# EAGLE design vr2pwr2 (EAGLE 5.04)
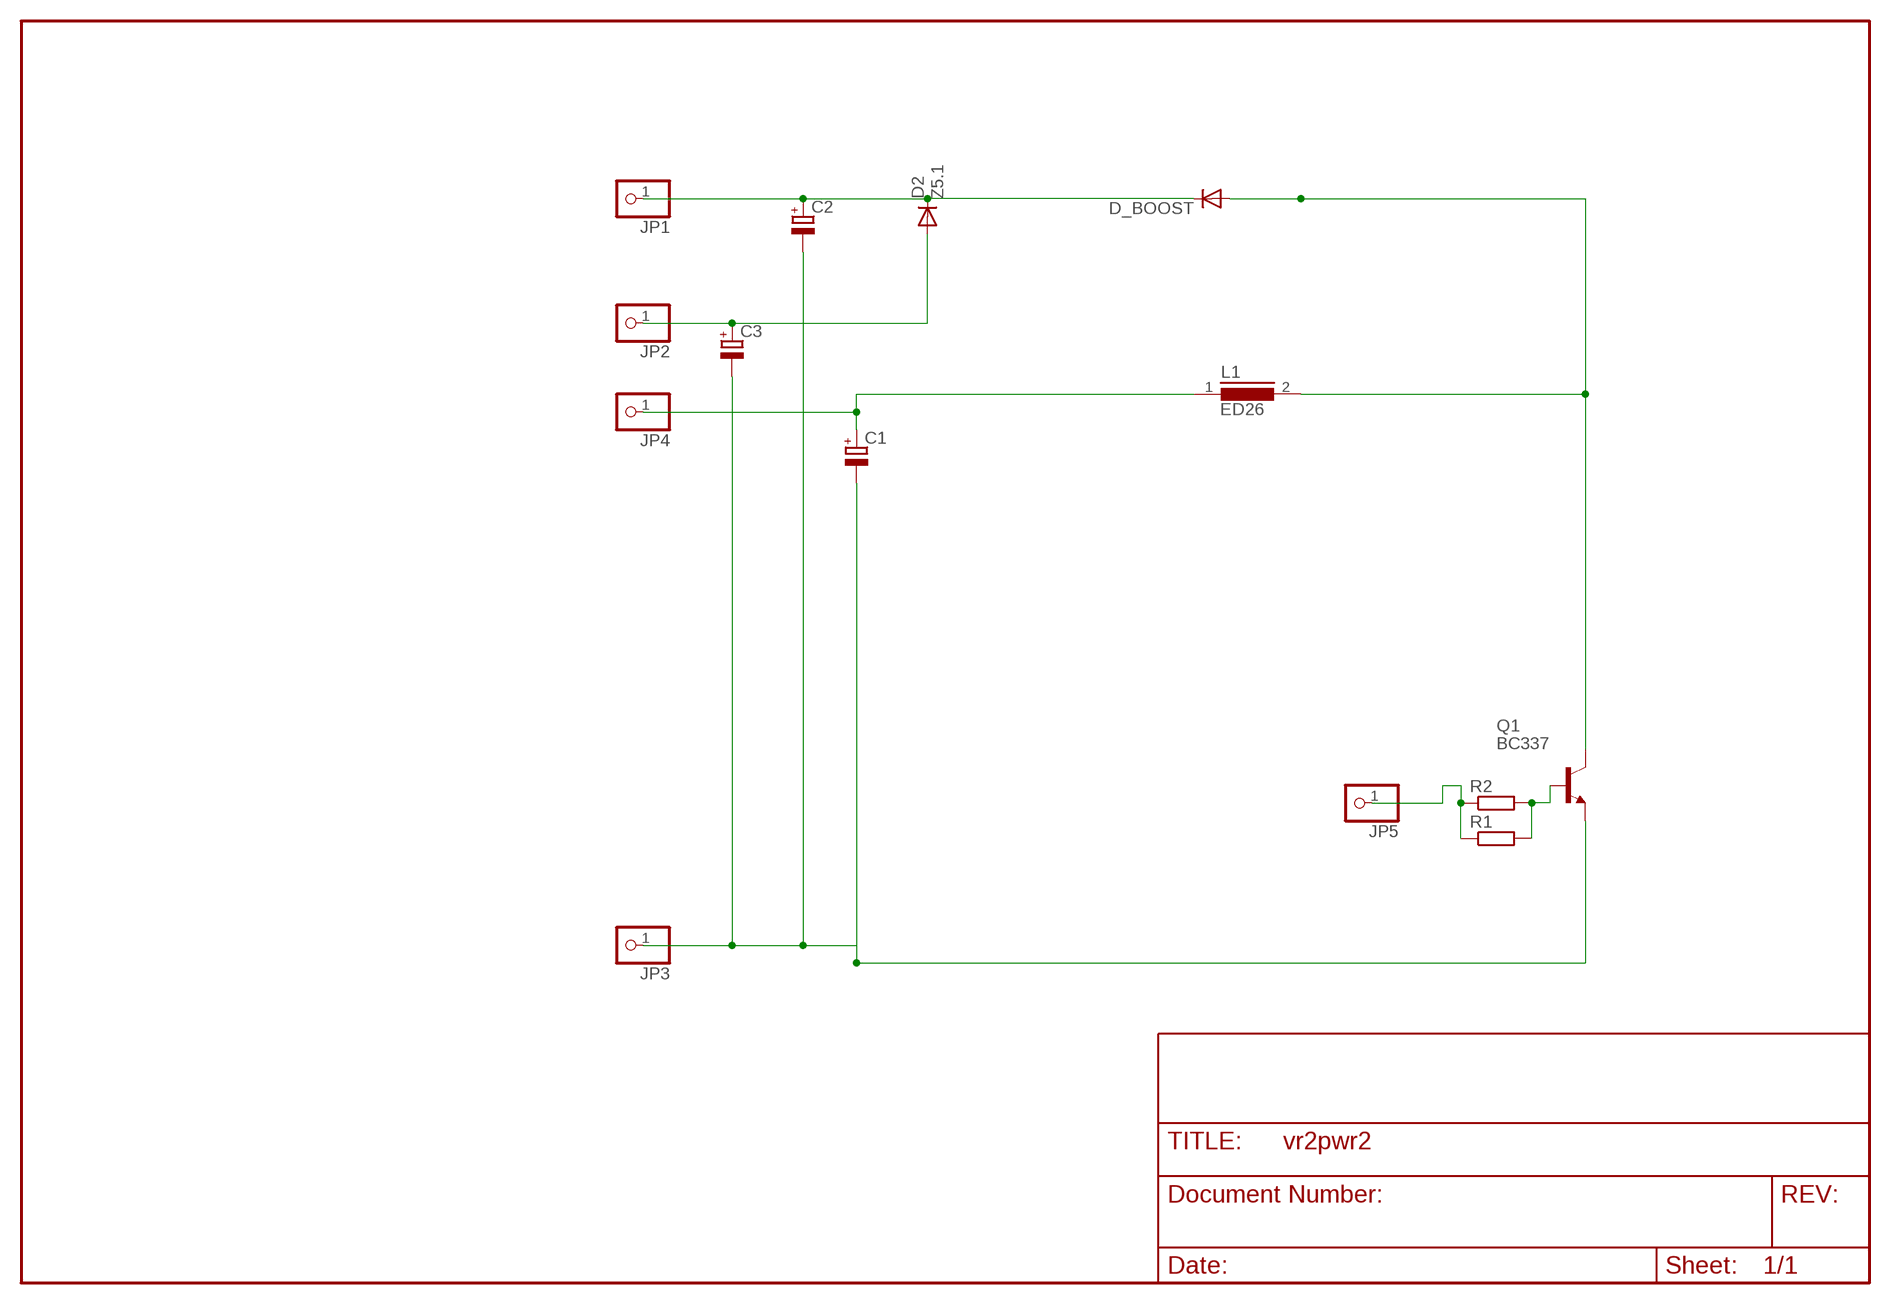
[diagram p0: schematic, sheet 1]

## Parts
C1  CPOL-EUE2.5-7  [E2,5-7]
C2  CPOL-EUE2.5-7  [E2,5-7]
C3  CPOL-EUE2-4  [E2-4]
D2  Z5.1  DIODE-D-2.5  [D-2.5]
D_BOOST  DIODE-D-10  [D-10]
JP1  PINHD-1X1  [1X01]
JP2  PINHD-1X1  [1X01]
JP3  PINHD-1X1  [1X01]
JP4  PINHD-1X1  [1X01]
JP5  PINHD-1X1  [1X01]
L1  ED26  [ED26]
Q1  BC337  [TO92]
R1  R-EU_R1206  [R1206]
R2  R-EU_R1206  [R1206]

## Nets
GND: C1.- C2.- C3.- JP3.1 Q1.1(E)
HOTSPOT: D_BOOST.A L1.2 Q1.3(C)
LOAD: C2.+ D2.C D_BOOST.C JP1.1
N$1: Q1.2(B) R1.2 R2.2
N$2: C1.+ JP4.1 L1.1
N$3: JP5.1 R1.1 R2.1
N$4: C3.+ D2.A JP2.1

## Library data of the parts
C1-C3 = rcl(2):CPOL-EU: POLARIZED CAPACITOR, European symbol
D2 D_BOOST = diode:DIODE-: DIODE
JP1-JP5 = pinhead:PINHD-1X1: PIN HEADER
L1 = inductors:ED26: INDUCTOR
Q1 = transistor-npn:BC337*: NPN Transistor
R1 R2 = rcl-2:R-EU_: RESISTOR, European symbol

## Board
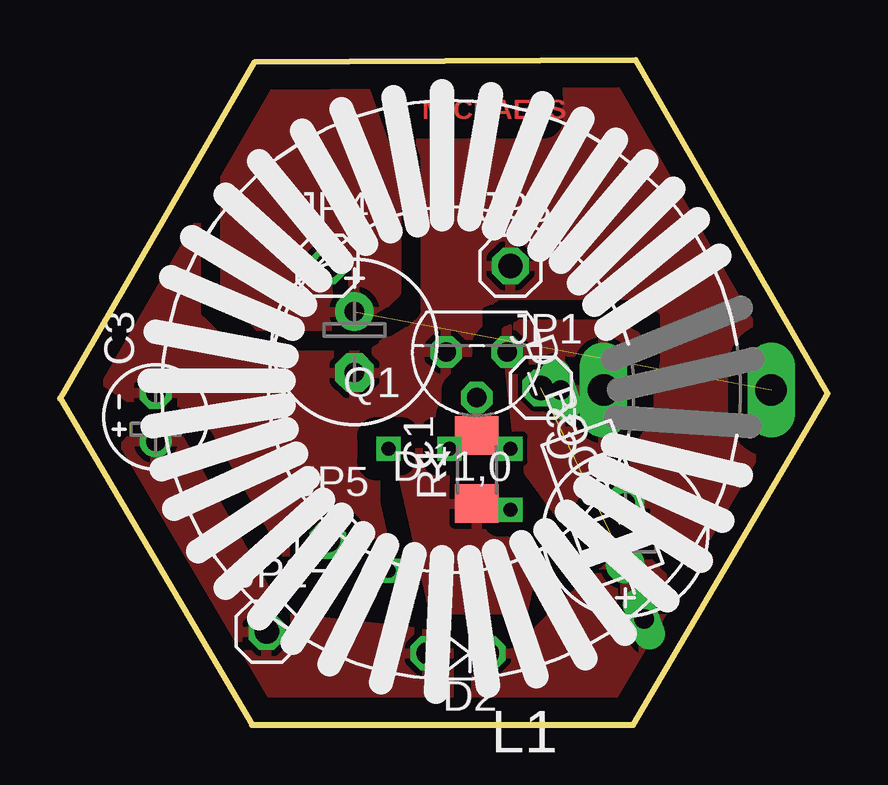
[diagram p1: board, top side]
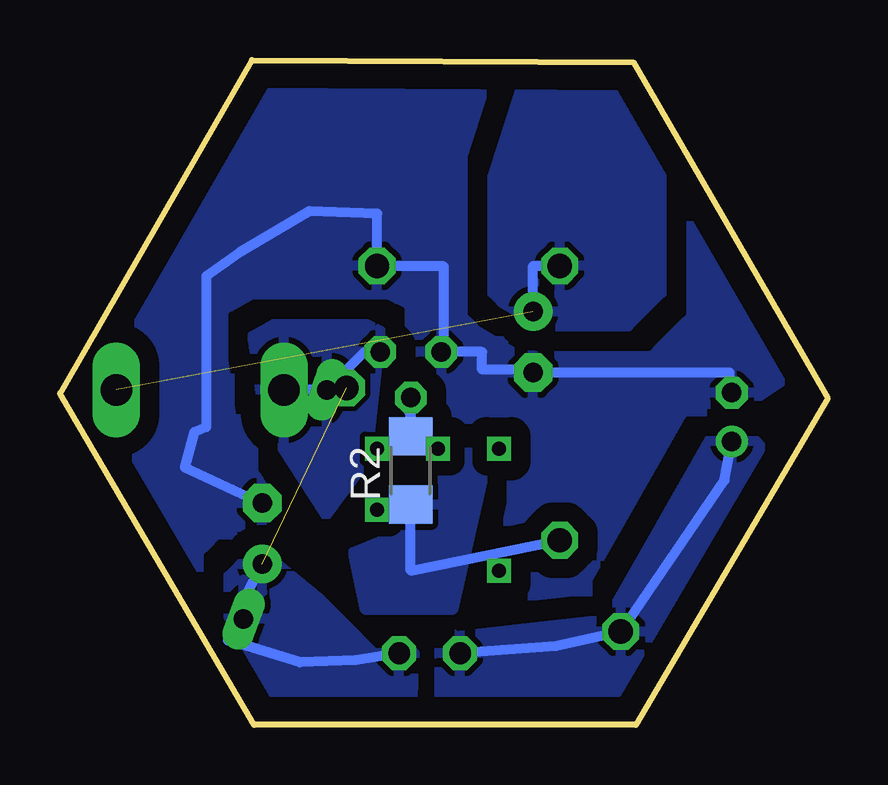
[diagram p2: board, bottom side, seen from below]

Size 32 x 27.7 mm. Coordinates in mm from the lower left corner, seen from the top.
Outline: 8,0 23.9,0 32,13.8 24,27.7 8.1,27.6 0,13.6 8,0
Copper layers (1*16): Top 0.035mm / dielectric 1.5mm / Bottom 0.035mm
Design rules "default": minimum track width 10mil, minimum drill 24mil, track to track 8mil, track to pad 8mil, pad to pad 8mil, via to via 8mil, smd to smd 8mil, copper to edge 40mil, drill to drill 8mil, minimum pad ring 10mil, minimum via ring 8mil, stop-mask expansion 4mil, vias tented up to drill 0mil, thermal gap 10mil

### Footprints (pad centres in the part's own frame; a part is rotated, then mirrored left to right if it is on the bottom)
E2,5-7 = drill 0.813 pad 1.6 round: + -1.27,0 | drill 0.813 pad 1.6 octagon: - 1.27,0
E2-4 = drill 0.813 pad 1.27 round: + -1.016,0 | drill 0.813 pad 1.27 octagon: - 1.016,0
D-2.5 = drill 0.9 octagon: A 1.27,0; C -1.27,0
D-10 = drill 0.813 long: A 5.08,0; C -5.08,0
1X01 = drill 1.016 octagon: 1 0,0
ED26 = drill 1.321 long: 1 -13.335,0; 2 -6.35,0
TO92 = drill 0.813 octagon: 1 1.27,0; 2 0,1.905; 3 -1.27,0
R1206 = smd 1.6 x 1.803: 1 -1.422,0; 2 1.422,0

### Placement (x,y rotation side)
C1  12.28,15.95 270 top
C2  23.57,7.96 90 top
C3  3.99,12.82 90 top
D2  16.59,2.98 180 top
D_BOOST  22.61,9.19 110 top
JP1  20.05,14.04 0 top
JP2  8.62,3.88 0 top
JP3  18.78,19.12 0 top
JP4  11.16,19.12 0 top
JP5  11.16,7.69 0 top
L1  16.31,13.96 180 top
Q1  17.37,15.54 180 top
R1  17.38,10.64 90 top
R2  17.38,10.6 90 bottom

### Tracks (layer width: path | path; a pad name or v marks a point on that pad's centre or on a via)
GND
  Bottom 0.406: C3.- 4.09,14.68 C1.- 12.28,14.8 14.4,14.8 14.4,15.54 Q1.1 16,15.54 16,19.1 18.78,19.1 JP3.1 18.78,21.3 21.6,21.4 24.5,19.7 25.9,18.7 25.9,12.4 26.4,12.2 26.8,10.73 C2.-
  pour Bottom (isolate 0.813, rank 3): 1.9,14.3 8.5,26.8 23.5,26.8 31.2,13.5 24.8,4.2 10.1,3.5 5.1,12.2
  pour Top (isolate 0.813, rank 3): 1.9,14.3 8.5,26.8 23.5,26.8 31.2,13.5 24.8,4.2 10.1,3.5 5.1,12.2
HOTSPOT
  Bottom 0.406: Q1.3 19.29,15.54 D_BOOST.A L1.2
  pour Bottom: 19.2,11 18.6,16.4 19.2,16.7 23.1,16.7 24,16.2 23.5,12.7 20.9,8.7
  pour Top: 19.2,11 18.6,16.4 19.2,16.7 23.1,16.7 24,16.2 23.5,12.7 20.9,8.7
LOAD  (1 unrouted)
  Bottom 0.406: C2.+ 24.98,3.93 D_BOOST.C 25,3.52 22,2.6 19.66,2.7 D2.C
  pour Bottom (isolate 0.61): 17.2,3 18.9,3 21.1,5.2 23.3,7 24.2,7 25,6.2 25,2.7 24.6,2.3 24.5,2.3 23,0.8 17.3,0.8
  pour Top (isolate 0.61): 17.3,3 19,3 21.2,5.2 23.4,7 24.3,7 25.1,6.2 25.1,2.7 24.7,2.3 24.6,2.3 23.1,0.8 17.4,0.8
N$1
  Top 0.406: Q1.2 R1.2
  Bottom 0.406: 17.37,11.42 R2.2 | 17.37,11.42 Q1.2 | 17.37,11.42 17.4,13.4 17.5,13.7
N$2  (1 unrouted)
  Bottom 0.406: JP4.1 12.28,19.12 C1.+
  pour Bottom (isolate 0.61): 11.9,16.6 8.3,16.6 6.9,18 6.9,23.6 7.9,26.5 12.8,26.5 14,22.8 14,18 13.6,17.6
  pour Top (isolate 0.61): 11.9,16.6 8.3,16.6 6.9,18 6.9,23.6 7.8,26.5 12.7,26.5 14,22.8 14,18 13.6,17.6
N$3
  Bottom 0.406: JP5.1 17.38,6.42 R2.1
  pour Bottom (isolate 0.61): 17.8,8 19.8,7.2 19.3,4.8 15.6,4.8 14.1,11.4 16.1,11.3
  pour Top (isolate 0.61): 17.8,8 19.8,7.2 19.3,4.8 15.6,4.8 14.1,11.4 16.1,11.3
N$4
  Bottom 0.406: D2.A 11.32,3.28 JP2.1 4.29,10.18 C3.+
  pour Bottom (isolate 0.61, rank 2): 15.6,3.8 15.8,3.8 16.2,3.4 16.2,0.8 16,0.6 8.4,0.6 2.4,11.2 3.3,12.2 4.8,12.1 9.2,4.4 15.5,3.7
  pour Top (isolate 0.61, rank 2): 15.6,3.9 15.8,3.9 16.2,3.5 16.2,0.9 16,0.7 8.4,0.7 2.4,11.3 3.3,12.3 4.8,12.2 9.2,4.5 15.5,3.8
N$5  (via drill 0.6)
  other vias: 18.78,11.5
N$6  (via drill 0.6)
  other vias: 18.78,8.96
N$7  (via drill 0.6)
  other vias: 16.24,11.5
N$8  (via drill 0.6)
  other vias: 13.7,11.5
N$9  (via drill 0.6)
  other vias: 13.7,6.42

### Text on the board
Top: MICHAELS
